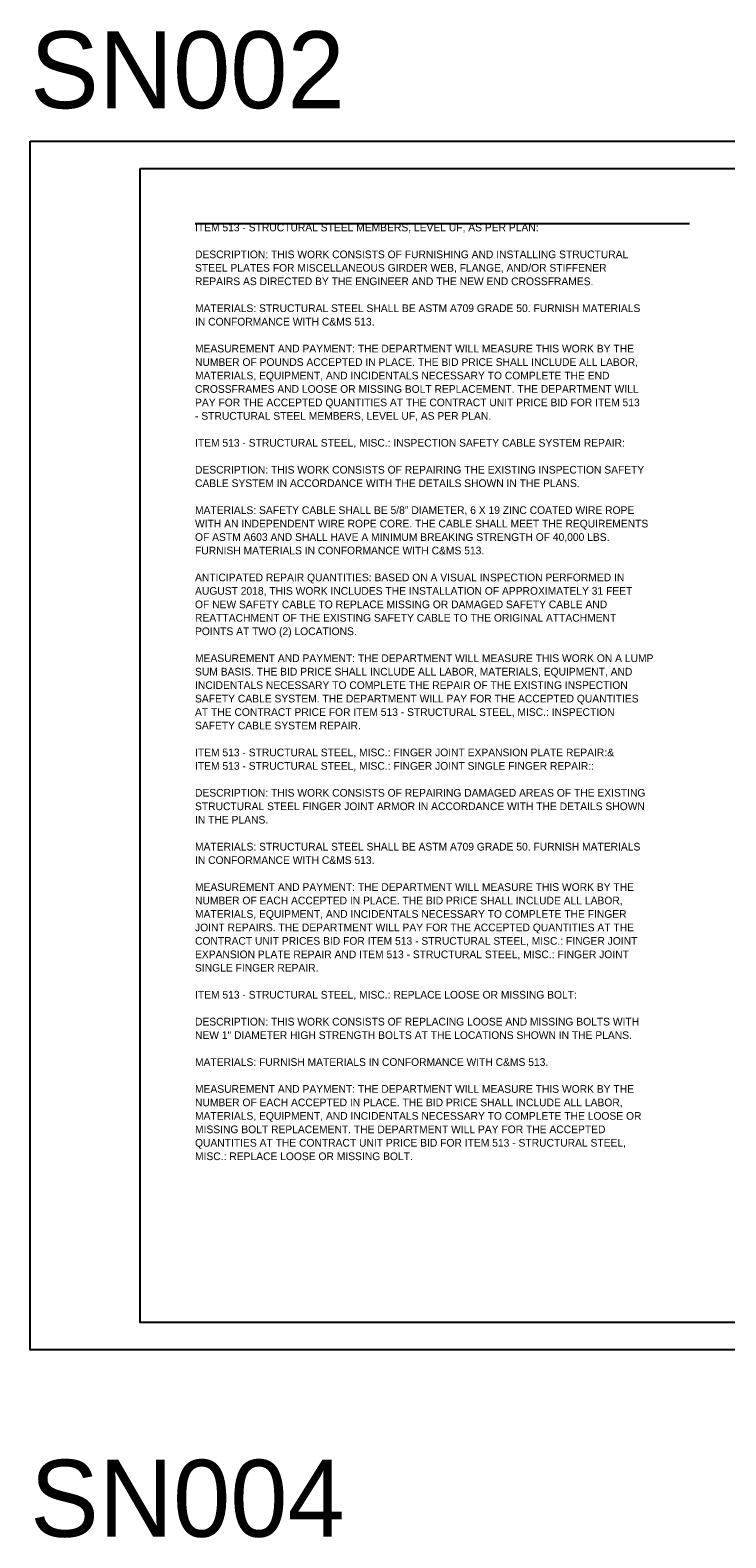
# Model space of a CAD drawing. Extents: x 0 to 72, y -26 to 50.
# Drawn here: x 38 to 50.66, y 22.58 to 50.02 of the extents above; entities that cross this region are included whole.
import ezdxf

# ---------------------------------------------------------------- set-up
doc = ezdxf.new("R2010")
doc.units = 0
doc.layers.add('SH_Cut_Line', color=7, linetype='Continuous')
doc.layers.add('SH_Data', color=7, linetype='Continuous')

msp = doc.modelspace()

# ---------------------------------------------------------------- linework, layer by layer
at = {"layer": 'SH_Cut_Line'}
msp.add_line((41, 46.5), (50, 46.5), dxfattribs=at)
for points in [[(38, 48), (72, 48), (72, 26), (38, 26)], [(40, 47.5), (70.5, 47.5), (70.5, 26.5), (40, 26.5)]]:
    msp.add_lwpolyline(points, close=True, dxfattribs=at)

# ---------------------------------------------------------------- texts
at = {"layer": 'SH_Data'}
for s, height, p in [('SN002', 1.4, (38, 48.6)), ('ITEM 513 - STRUCTURAL STEEL MEMBERS, LEVEL UF, AS PER PLAN:', 0.14, (41, 46.36)), ('ITEM 513 - STRUCTURAL STEEL MEMBERS, LEVEL UF, AS PER PLAN:', 0.14, (41, 46.36)), ('DESCRIPTION: THIS WORK CONSISTS OF FURNISHING AND INSTALLING STRUCTURAL ', 0.14, (41, 45.87)), ('STEEL PLATES FOR MISCELLANEOUS GIRDER WEB, FLANGE, AND/OR STIFFENER ', 0.14, (41, 45.625)), ('REPAIRS AS DIRECTED BY THE ENGINEER AND THE NEW END CROSSFRAMES.', 0.14, (41, 45.38)), ('MATERIALS: STRUCTURAL STEEL SHALL BE ASTM A709 GRADE 50. FURNISH MATERIALS ', 0.14, (41, 44.89)), ('IN CONFORMANCE WITH C&MS 513.', 0.14, (41, 44.645)), ('MEASUREMENT AND PAYMENT: THE DEPARTMENT WILL MEASURE THIS WORK BY THE ', 0.14, (41, 44.155)), ('NUMBER OF POUNDS ACCEPTED IN PLACE. THE BID PRICE SHALL INCLUDE ALL LABOR, ', 0.14, (41, 43.91)), ('MATERIALS, EQUIPMENT, AND INCIDENTALS NECESSARY TO COMPLETE THE END ', 0.14, (41, 43.665)), ('CROSSFRAMES AND LOOSE OR MISSING BOLT REPLACEMENT. THE DEPARTMENT WILL ', 0.14, (41, 43.42)), ('PAY FOR THE ACCEPTED QUANTITIES AT THE CONTRACT UNIT PRICE BID FOR ITEM 513 ', 0.14, (41, 43.175)), ('- STRUCTURAL STEEL MEMBERS, LEVEL UF, AS PER PLAN.', 0.14, (41, 42.93)), ('ITEM 513 - STRUCTURAL STEEL, MISC.: INSPECTION SAFETY CABLE SYSTEM REPAIR:', 0.14, (41, 42.44)), ('ITEM 513 - STRUCTURAL STEEL, MISC.: INSPECTION SAFETY CABLE SYSTEM REPAIR:', 0.14, (41, 42.44)), ('DESCRIPTION: THIS WORK CONSISTS OF REPAIRING THE EXISTING INSPECTION SAFETY ', 0.14, (41, 41.95)), ('CABLE SYSTEM IN ACCORDANCE WITH THE DETAILS SHOWN IN THE PLANS.', 0.14, (41, 41.705)), ('MATERIALS: SAFETY CABLE SHALL BE 5/8" DIAMETER, 6 X 19 ZINC COATED WIRE ROPE ', 0.14, (41, 41.215)), ('WITH AN INDEPENDENT WIRE ROPE CORE. THE CABLE SHALL MEET THE REQUIREMENTS ', 0.14, (41, 40.97)), ('OF ASTM A603 AND SHALL HAVE A MINIMUM BREAKING STRENGTH OF 40,000 LBS. ', 0.14, (41, 40.725)), ('FURNISH MATERIALS IN CONFORMANCE WITH C&MS 513.', 0.14, (41, 40.48)), ('ANTICIPATED REPAIR QUANTITIES: BASED ON A VISUAL INSPECTION PERFORMED IN ', 0.14, (41, 39.99)), ('AUGUST 2018, THIS WORK INCLUDES THE INSTALLATION OF APPROXIMATELY 31 FEET ', 0.14, (41, 39.745)), ('OF NEW SAFETY CABLE TO REPLACE MISSING OR DAMAGED SAFETY CABLE AND ', 0.14, (41, 39.5)), ('REATTACHMENT OF THE EXISTING SAFETY CABLE TO THE ORIGINAL ATTACHMENT ', 0.14, (41, 39.255)), ('POINTS AT TWO (2) LOCATIONS.', 0.14, (41, 39.01)), ('SUM BASIS. THE BID PRICE SHALL INCLUDE ALL LABOR, MATERIALS, EQUIPMENT, AND ', 0.14, (41, 38.275)), ('MEASUREMENT AND PAYMENT: THE DEPARTMENT WILL MEASURE THIS WORK ON A LUMP ', 0.14, (41, 38.52)), ('INCIDENTALS NECESSARY TO COMPLETE THE REPAIR OF THE EXISTING INSPECTION ', 0.14, (41, 38.03)), ('SAFETY CABLE SYSTEM. THE DEPARTMENT WILL PAY FOR THE ACCEPTED QUANTITIES ', 0.14, (41, 37.785)), ('AT THE CONTRACT PRICE FOR ITEM 513 - STRUCTURAL STEEL, MISC.: INSPECTION ', 0.14, (41, 37.54)), ('SAFETY CABLE SYSTEM REPAIR.', 0.14, (41, 37.295)), ('ITEM 513 - STRUCTURAL STEEL, MISC.: FINGER JOINT EXPANSION PLATE REPAIR &', 0.14, (41, 36.805)), ('ITEM 513 - STRUCTURAL STEEL, MISC.: FINGER JOINT EXPANSION PLATE REPAIR:', 0.14, (41, 36.805)), ('ITEM 513 - STRUCTURAL STEEL, MISC.: FINGER JOINT SINGLE FINGER REPAIR :', 0.14, (41, 36.56)), ('ITEM 513 - STRUCTURAL STEEL, MISC.: FINGER JOINT SINGLE FINGER REPAIR:', 0.14, (41, 36.56)), ('STRUCTURAL STEEL FINGER JOINT ARMOR IN ACCORDANCE WITH THE DETAILS SHOWN ', 0.14, (41, 35.825)), ('DESCRIPTION: THIS WORK CONSISTS OF REPAIRING DAMAGED AREAS OF THE EXISTING ', 0.14, (41, 36.07)), ('IN THE PLANS. ', 0.14, (41, 35.58)), ('MATERIALS: STRUCTURAL STEEL SHALL BE ASTM A709 GRADE 50. FURNISH MATERIALS ', 0.14, (41, 35.09)), ('IN CONFORMANCE WITH C&MS 513.', 0.14, (41, 34.845)), ('MEASUREMENT AND PAYMENT: THE DEPARTMENT WILL MEASURE THIS WORK BY THE ', 0.14, (41, 34.355)), ('NUMBER OF EACH ACCEPTED IN PLACE. THE BID PRICE SHALL INCLUDE ALL LABOR, ', 0.14, (41, 34.11)), ('JOINT REPAIRS. THE DEPARTMENT WILL PAY FOR THE ACCEPTED QUANTITIES AT THE ', 0.14, (41, 33.62)), ('MATERIALS, EQUIPMENT, AND INCIDENTALS NECESSARY TO COMPLETE THE FINGER ', 0.14, (41, 33.865)), ('CONTRACT UNIT PRICES BID FOR ITEM 513 - STRUCTURAL STEEL, MISC.: FINGER JOINT ', 0.14, (41, 33.375)), ('EXPANSION PLATE REPAIR AND ITEM 513 - STRUCTURAL STEEL, MISC.: FINGER JOINT ', 0.14, (41, 33.13)), ('SINGLE FINGER REPAIR.', 0.14, (41, 32.885)), ('ITEM 513 - STRUCTURAL STEEL, MISC.: REPLACE LOOSE OR MISSING BOLT:', 0.14, (41, 32.395)), ('ITEM 513 - STRUCTURAL STEEL, MISC.: REPLACE LOOSE OR MISSING BOLT:', 0.14, (41, 32.395)), ('DESCRIPTION: THIS WORK CONSISTS OF REPLACING LOOSE AND MISSING BOLTS WITH ', 0.14, (41, 31.905)), ('NEW 1" DIAMETER HIGH STRENGTH BOLTS AT THE LOCATIONS SHOWN IN THE PLANS. ', 0.14, (41, 31.66)), ('MATERIALS: FURNISH MATERIALS IN CONFORMANCE WITH C&MS 513.', 0.14, (41, 31.17)), ('MEASUREMENT AND PAYMENT: THE DEPARTMENT WILL MEASURE THIS WORK BY THE ', 0.14, (41, 30.68)), ('NUMBER OF EACH ACCEPTED IN PLACE. THE BID PRICE SHALL INCLUDE ALL LABOR, ', 0.14, (41, 30.435)), ('MATERIALS, EQUIPMENT, AND INCIDENTALS NECESSARY TO COMPLETE THE LOOSE OR ', 0.14, (41, 30.19)), ('MISSING BOLT REPLACEMENT. THE DEPARTMENT WILL PAY FOR THE ACCEPTED ', 0.14, (41, 29.945)), ('QUANTITIES AT THE CONTRACT UNIT PRICE BID FOR ITEM 513 - STRUCTURAL STEEL, ', 0.14, (41, 29.7)), ('MISC.: REPLACE LOOSE OR MISSING BOLT.', 0.14, (41, 29.455)), ('SN004', 1.4, (38, 22.6))]:
    msp.add_text(s, height=height, dxfattribs=at).set_placement(p)

doc.saveas('drawing.dxf')
